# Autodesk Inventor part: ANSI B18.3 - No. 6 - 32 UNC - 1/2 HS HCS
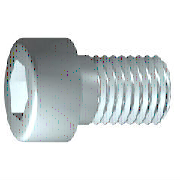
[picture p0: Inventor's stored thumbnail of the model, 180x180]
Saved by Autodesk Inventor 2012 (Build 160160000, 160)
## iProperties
IsCustomPart: 0
Created: 2011-02
Part Number: ANSI B18.3 - No. 6 - 32 UNC - 1/2 HS HCS
Material: Steel, Mild
Description: Hexagon Socket Head Cap Screw
Document SubType Name: Modeling
Standard: ANSI B18.3
Designer: Owner
Standard Revision: 2003
Standards Organization: ANSI
Language: en-US
Size Designation: No. 6 - 32 UNC - 1/2
Categories: <MemberInstance><Categories><Category DisplayName="Fasteners" InternalName="e4da775c-781d-43d5-af7c-5136215cf5a6" Mnemonic="FSTN"><Category DisplayName="Bolts"
Density: 7.86 g/cm^3
Mass: 1.56088 g
Surface Area: 2.65687 cm^2
Volume: 0.198585 cm^3
Author: Owner
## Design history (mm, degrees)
body "Solid1"
workplane "Work Plane1"
fillet "Fillet2" dims "d30" = 0.127 (= R)
revolve "Body" stored, may be unused: angle "d10" = 90 deg
sketch "Sketch2"
  geometry: L1 (0, -4.018)-(0, 4.018) reference; L2 (-4.018, 0)-(4.018, 0) reference; L3 (1.598, 0)-(0.799, -1.384); L4 (0.799, -1.384)-(-0.799, -1.384); L5 (-0.799, -1.384)-(-1.598, 0); L6 (-1.598, 0)-(-0.799, 1.384); L7 (-0.799, 1.384)-(0.799, 1.384); L8 (0.799, 1.384)-(1.598, 0); 2 further points
  constraints: 12 end point, 1 coincident, 1 horizontal alignment, 1 point on line, 12 other
extrude "Slot" join sketch "Sketch2" stored distance "d11" = 10; taper "d12" = 0 deg
fillet "Fillet1" dims "d17" = 0.3302 (= RR)
feature "Thread" dims "d13" = 10.71555 (= GEL), "d14" = 0
chamfer "Chamfer1" distance "d15" = 0.47244 (= -0.5 x SPD + 0.5 x GD); stored, may be unused: second distance "d16" = 0.47244 (= GUL), angle "d27" = 45 deg
sketch "Sketch1"
  geometry: L1 (-0.957, 0)-(12.7, 0); L2 (12.7, 0)-(12.7, 1.753); L3 (12.7, 1.753)-(1.984, 1.753); L4 (1.984, 1.753)-(0, 1.753); L5 (0, 1.753)-(0, 1.753); L6 (0, 1.753)-(0, 2.87); L7 (0, 2.87)-(-3.505, 2.87); L8 (-3.505, 2.87)-(-3.505, 1.598); L9 (-3.505, 1.598)-(-1.88, 1.598); L10 (-1.88, 1.598)-(-0.957, 0); L11 (-6.746, 0)-(15.941, 0) reference; L12 (0, -0.574)-(0, 3.444) reference; L13 (1.984, 1.753)-(0, 1.753)
  constraints: 22 end point, 6 parallel, 2 collinear, 2 perpendicular, 1 horizontal, 1 point on line
  dimensions: "d1" = 10.71555 distance from line of L3.end L2 (= GEL); "d2" = 1.98435 distance of L4.end L3.end (computed from GAL); "d3" = 3.5052 distance between parallel lines of L8 L6 (= KOH); "d4" = 1.6256 distance of L8.end L9.end (= INTI); "d5" = 60 deg angle of L10 L1; "d6" = 3.5052 diameter of L3 L1 (= GD); "d7" = 3.5052 diameter of L5 L1 (= BDM); "d8" = 3.1969 diameter of L9 L1 (= 1.1547 x SW); "d9" = 5.7404 diameter of L7 L1 (= KOD); "d26" = 12.7 distance between parallel lines of L12 L2 (= NLG)
other parameters: "GD" = 3.5052 [user parameter; used in 2 equation terms], "NLG" = 12.7 [user parameter; used in 1 equation term], "GEL" = 10.71555 [user parameter; used in 2 equation terms], "KOD" = 5.7404 [user parameter; used in 1 equation term], "KOH" = 3.5052 [user parameter; used in 1 equation term], "INTI" = 1.6256 [user parameter; used in 1 equation term], "GAL" = 1.98425 [user parameter; used in 1 equation term], "GUL" = 0.47244 [user parameter; used in 1 equation term], "BDM" = 3.5052 [user parameter; used in 1 equation term], "SW" = 2.7686 [user parameter; used in 2 equation terms], "RR" = 0.3302 [user parameter; used in 1 equation term], "SPD" = 2.56032 [user parameter; used in 2 equation terms], "d19" = 0, "d28" = 0, "d29" = 0, "R" = 0.127 [user parameter; used in 1 equation term], "PHH" = 0.127 [user parameter], "GD1" = 2.56032 (= SPD) [user parameter], "THREADDIA" = 3.5052 [user parameter], "FAWI" = 45 deg [user parameter], "PTC" = 0.79375 (computed from TPU) [user parameter], "KOH1" = 3.1496 [user parameter], "NND" = 3.5052 [user parameter], "TOA" = 30 deg [user parameter], "E0" = 3.19773 (= 1.155 x SW) [user parameter]
